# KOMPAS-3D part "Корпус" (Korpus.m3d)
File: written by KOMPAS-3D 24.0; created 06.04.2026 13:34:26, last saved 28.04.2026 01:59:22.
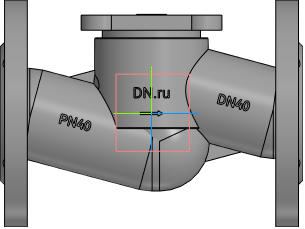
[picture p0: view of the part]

Document properties: Автор: R2D2; Полное имя файла: C:\Работа\ГОТОВЫЕ ИСХОДНИКИ\VSO2130M-F-S Клапан запорный сильфонный DN.ru Ду15-100 Ру40\исходные материалы\DN40\Korpus.m3d

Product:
- Body: Труба / Нестандартная труба / L = 128.1 мм  | qty 1  | 2 such rows
    Материал: Нестандартная труба (density 7856 kg/m3)
    Масса: 9.898009
    Раздел спецификации: Детали
    Примечание: 2,84 кг
    additional columns: Pipeline; 0.06; 0; 0; 0.002; 0.12807; true; 0.04
- Body: Тело 4  | qty 1
    Материал: Нестандартная труба (density 7856 kg/m3)
    Масса: 9.898009
- Body: Тело 5  | qty 1
    Материал: Нестандартная труба (density 7856 kg/m3)
    Масса: 9.898009
- Body: Тело 8  | qty 1
    Материал: Нестандартная труба (density 7856 kg/m3)
    Масса: 9.898009
- Body: Тело 10  | qty 1
    Материал: Нестандартная труба (density 7856 kg/m3)
    Масса: 9.898009
- Body: Тело 11  | qty 1
    Материал: Нестандартная труба (density 7856 kg/m3)
    Масса: 9.898009
- Body: Тело 12  | qty 1
    Материал: Нестандартная труба (density 7856 kg/m3)
    Масса: 9.898009
- Body: Тело 13  | qty 1
    Материал: Нестандартная труба (density 7856 kg/m3)
    Масса: 9.898009
- Part/product: Корпус
    Масса: 6.9

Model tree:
1. Труба:1  (labels: {F703FF30-5BE6-4673-A7F1-8EDA1BE1E2D1}; SHAPEOBJECT3D_ATTR_BUTT; SHAPEOBJECT3D_ATTR_VALID; SHAPEOBJECT3D_ATTR_BUTT_AREA)
     PIPE_R = 3
2. Труба:2  (labels: {F703FF30-5BE6-4673-A7F1-8EDA1BE1E2D1}; SHAPEOBJECT3D_ATTR_BUTT; SHAPEOBJECT3D_ATTR_VALID; SHAPEOBJECT3D_ATTR_BUTT_AREA)
     PIPE_R = 3
3. Колонна
4. Элемент выдавливания:1
     Смещение 1 = -1; Смещение 2 = -5
5. Скругление:17  (with: Ребро.Элемент выдавливания:1)
     Радиус = 0.6
6. Скругление:18  (with: Ребро.Элемент выдавливания:1)
7. Скругление:24
     Радиус = 1.5
8. Элемент выдавливания:2
     Расстояние 1 = 6
9. Эскиз:4  (with: Грань.Элемент выдавливания:1)
10. Элемент выдавливания:3
     Расстояние 1 = 5
11. ОТЛИВКА
12. Скругление:6  (with: Грань.Элемент выдавливания:1)
     Радиус = 2
13. Элемент выдавливания:6  (with: Грань.Элемент выдавливания:1)
     Смещение 1 = 4
14. ЛЕЙБЛ
15. Элемент выдавливания:7  (with: Грань.Элемент выдавливания:1)
     Расстояние 1 = 38.4753; Смещение 1 = 1
16. Dn
17. Pn
18. Стрелочка
19. Элемент выдавливания:10  (with: Грань.Труба:1)
     Расстояние 1 = 30.999; Смещение 1 = 1
20. Элемент выдавливания:11  (with: Грань.Труба:2)
     Расстояние 1 = 30.9306; Смещение 1 = 1
21. Элемент выдавливания:12  (with: Грань.Элемент выдавливания:1)
     Расстояние 1 = 38.4998; Смещение 1 = 1
22. Материал
23. Элемент выдавливания:13  (with: Грань.Элемент выдавливания:1)
     Расстояние 1 = 37.9932; Смещение 1 = 0.5
24. Фланец верх  (with: Грань.Элемент выдавливания:3)
25. Элемент выдавливания:14
     Расстояние 1 = 10
26. Эскиз:18  (with: Грань.Элемент выдавливания:14)
27. Элемент выдавливания:15
     Расстояние 1 = 0.5
28. Эскиз:19  (with: Грань.Элемент выдавливания:14, Ребро.Элемент выдавливания:14)
29. Элемент выдавливания:16  (with: Грань.Элемент выдавливания:14)
     Расстояние 1 = 0.5; Расстояние 2 = 11; Смещение 2 = 1
30. Фланец
31. Элемент вращения:1
     Угол 1 = 360
32. отвертие во фланце  (with: Грань.Элемент вращения:1)
33. Элемент выдавливания:8
34. Массив по концентрической сетке:2  (with: Элемент выдавливания:8, Эскиз:10, Грань.Элемент вращения:1)  (4 pattern instances)
     Шаг 2 = 360
35. Зеркальный массив:1
36. Экземпляр ( 1 )
37. Экземпляр ( 2 )  (with: Элемент вращения:1, Массив по концентрической сетке:2, Экземпляр ( 1 ), Элемент выдавливания:8)
38. Экземпляр ( 3 )  (with: Элемент выдавливания:8)
39. Экземпляр ( 4 )  (with: Элемент выдавливания:8)
40. Скругление:25  (with: Ребро.Элемент выдавливания:1)
     Радиус = 0.6
41. Массив по концентрической сетке:3  (with: Элемент выдавливания:16, Эскиз:19)  (labels: Клапан запорный DN.ru Ду40 Ру40)  (4 pattern instances)
     Шаг 2 = 360

Expressions: DS/2+3; DN/2; LL/2; D1/2; D2/2-10
Referenced files in C:\Работа\ГОТОВЫЕ ИСХОДНИКИ\VSO2130M-F-S Клапан запорный сальниковый DN.ru Ду15-100 Ру40\исходные материалы\DN40\: VSO2130M-F-S Клапан запорный DN.ru Ду40 Ру40.a3d
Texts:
  GOST 26.020 Pr3
  var3D
  GS-C25
  смещение колонны вниз
  LL-10
  DN+20
  DS+10
  Труба / Нестандартная труба / L = %s мм
  Ось Y.Начало координат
